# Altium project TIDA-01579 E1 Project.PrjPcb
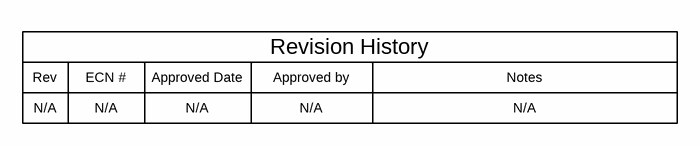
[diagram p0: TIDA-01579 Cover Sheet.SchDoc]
CopyrightYear: 2018; PCB_Layout: Barrett Bryan; PCB_Rev: E1; PRJ_Customer: Public Release; PRJ_Engineer: Srinivasan Iyer; PRJ_Number: TIDA-01579; PRJ_Title: TIDA-01579 Video Doorbell Power; SCH_Rev: E1; TechSupport: http://www.ti.com/support; TID: TIDA-01579
4 sheets, 208 parts. Net scope: global (net labels, ports and power ports of the same name join across sheets).
Board file: PCB-08.PcbDoc
Sheets:
  TIDA-01579 Cover Sheet.SchDoc
  TIDA-01579 Point of Load.SchDoc
  TIDA-01579 Other.SchDoc
  EVM_Hardware.SchDoc

## Sheet TIDA-01579 Cover Sheet.SchDoc
size 431 x 279 mm; Date: Not shown in title block; ApprovedBy: Not shown in title block; CheckedBy: Not shown in title block; Author: Not shown in title block; CompanyName: Not shown in title block; Engineer: Not shown in title block; Organization: Not shown in title block; Address1: Not shown in title block; Address2: Not shown in title block; Address3: Not shown in title block; Address4: Not shown in title block; DocumentNumber: 1; Revision: Use project parameter SCH_Rev; SheetNumber: 1; SheetTotal: 3; PageSetup: Record=PageOptions¦CenterHorizontal=True¦CenterVertical=True¦PrintScale=1.00¦XCorrection=1.00¦YCorrection=1.00¦PrintKind=0¦BorderSize=5000000¦LeftOffset=0¦BottomOffset=0¦Orientation=2¦PaperLength=1000¦PaperWidth=1000¦Scale=100¦PaperSource=15¦PrintQuality=600¦MediaType=1¦DitherType=10¦PaperKind=Letter¦PrintScaleMode=1

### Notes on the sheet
- Rev
- N/A
- ECN #
- Approved Date
- Approved by
- Revision History
- Notes

## Sheet TIDA-01579 Point of Load.SchDoc: Point of load converters
size 431 x 279 mm; Date: Not shown in title block; ApprovedBy: Not shown in title block; CheckedBy: Not shown in title block; Author: Not shown in title block; CompanyName: Not shown in title block; DrawnBy: Barrett Bryan; Engineer: Not shown in title block; Organization: Not shown in title block; Address1: Not shown in title block; Address2: Not shown in title block; Address3: Not shown in title block; Address4: Not shown in title block; DocumentNumber: 1; Revision: Use project parameter SCH_Rev; SheetNumber: 2; SheetTotal: 3; PageSetup: Record=PageOptions¦CenterHorizontal=True¦CenterVertical=True¦PrintScale=1.00¦XCorrection=1.00¦YCorrection=1.00¦PrintKind=0¦BorderSize=5000000¦LeftOffset=0¦BottomOffset=0¦Orientation=2¦PaperLength=1000¦PaperWidth=1000¦Scale=100¦PaperSource=15¦PrintQuality=600¦MediaType=1¦DitherType=10¦PaperKind=Letter¦PrintScaleMode=1
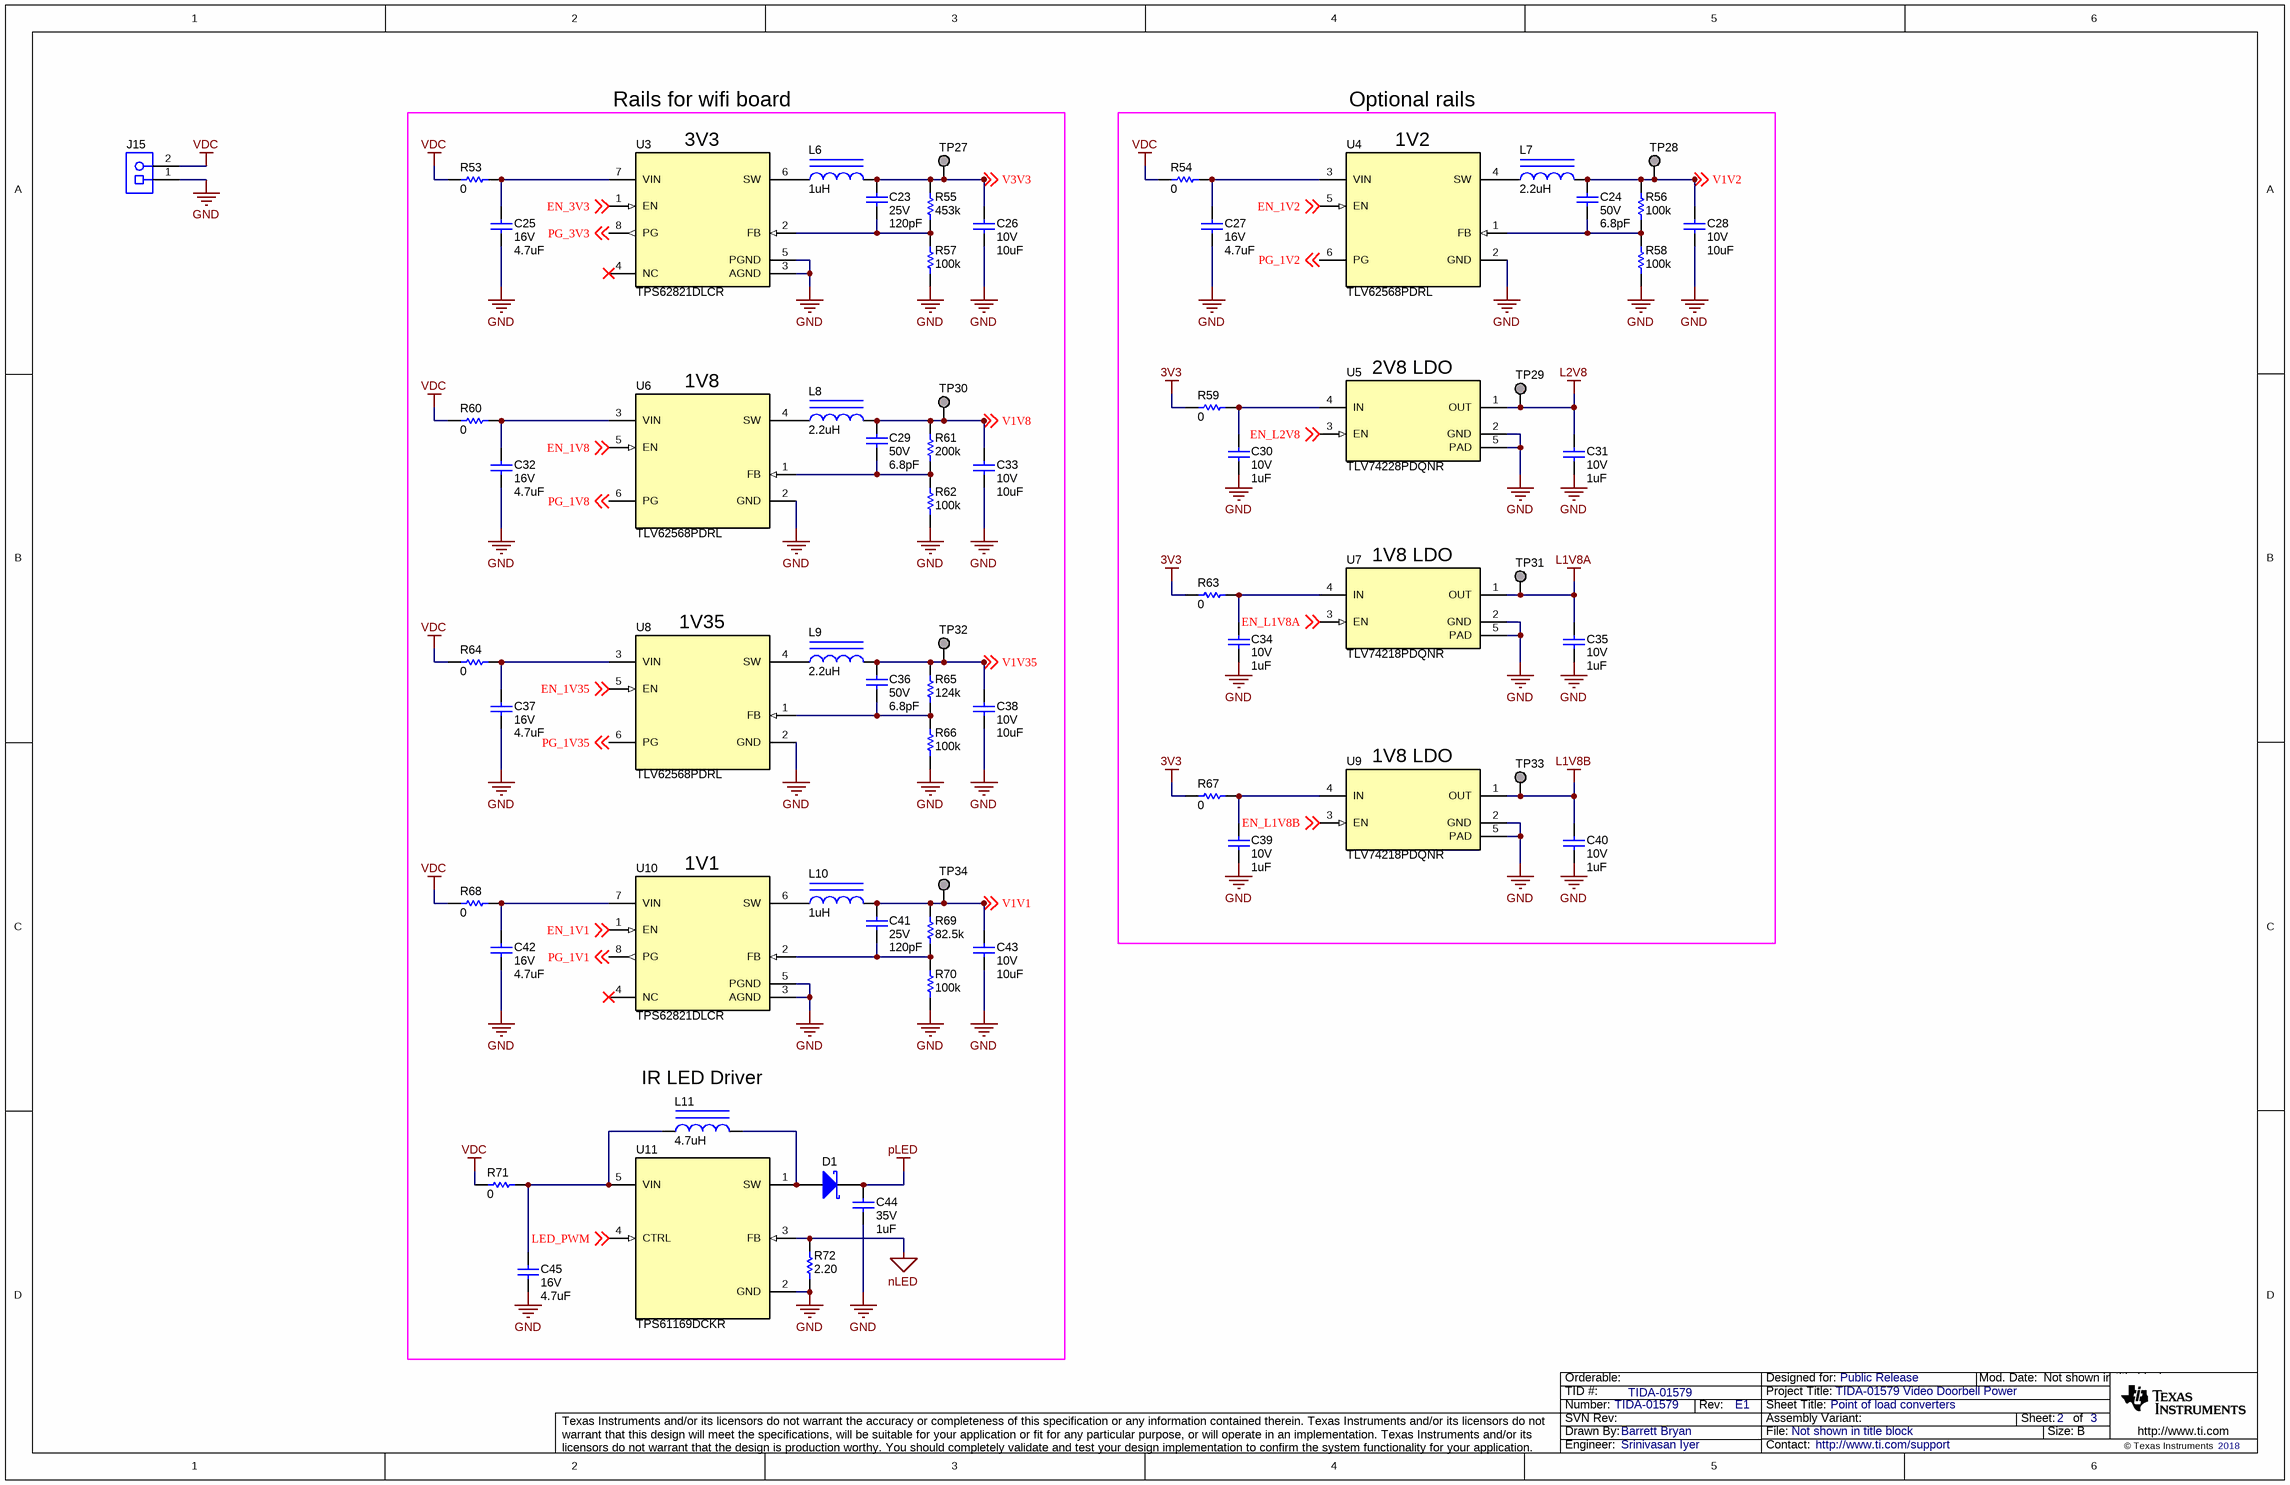
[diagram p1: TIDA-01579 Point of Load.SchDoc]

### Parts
C23  VDC_V: 25V  ValueDisplayed: 120pF  [0201]  (hidden comment: GRM033R71E121KA01D)
C24  VDC_V: 50V  ValueDisplayed: 6.8pF  [0201]  (hidden comment: GRM0335C1H6R8BA01D)
C25  VDC_V: 16V  ValueDisplayed: 4.7uF  [0603S]  (hidden comment: GRM188Z71C475KE21D)
C26  VDC_V: 10V  ValueDisplayed: 10uF  [0603]  (hidden comment: GRM188Z71A106MA73D)
C27  VDC_V: 16V  ValueDisplayed: 4.7uF  [0603]  (hidden comment: GRM188Z71C475KE21D)
C28  VDC_V: 10V  ValueDisplayed: 10uF  [0603]  (hidden comment: GRM188Z71A106MA73D)
C29  VDC_V: 50V  ValueDisplayed: 6.8pF  [0201]  (hidden comment: GRM0335C1H6R8BA01D)
C30  VDC_V: 10V  ValueDisplayed: 1uF  [0402]  (hidden comment: GRM155R61A105KE15D)
C31  VDC_V: 10V  ValueDisplayed: 1uF  [0402]  (hidden comment: GRM155R61A105KE15D)
C32  VDC_V: 16V  ValueDisplayed: 4.7uF  [0603]  (hidden comment: GRM188Z71C475KE21D)
C33  VDC_V: 10V  ValueDisplayed: 10uF  [0603]  (hidden comment: GRM188Z71A106MA73D)
C34  VDC_V: 10V  ValueDisplayed: 1uF  [0402]  (hidden comment: GRM155R61A105KE15D)
C35  VDC_V: 10V  ValueDisplayed: 1uF  [0402]  (hidden comment: GRM155R61A105KE15D)
C36  VDC_V: 50V  ValueDisplayed: 6.8pF  [0201]  (hidden comment: GRM0335C1H6R8BA01D)
C37  VDC_V: 16V  ValueDisplayed: 4.7uF  [0603]  (hidden comment: GRM188Z71C475KE21D)
C38  VDC_V: 10V  ValueDisplayed: 10uF  [0603]  (hidden comment: GRM188Z71A106MA73D)
C39  VDC_V: 10V  ValueDisplayed: 1uF  [0402]  (hidden comment: GRM155R61A105KE15D)
C40  VDC_V: 10V  ValueDisplayed: 1uF  [0402]  (hidden comment: GRM155R61A105KE15D)
C41  VDC_V: 25V  ValueDisplayed: 120pF  [0201]  (hidden comment: GRM033R71E121KA01D)
C42  VDC_V: 16V  ValueDisplayed: 4.7uF  [0603S]  (hidden comment: GRM188Z71C475KE21D)
C43  VDC_V: 10V  ValueDisplayed: 10uF  [0603]  (hidden comment: GRM188Z71A106MA73D)
C44  VDC_V: 35V  ValueDisplayed: 1uF  [0603]  (hidden comment: C1608X7R1V105K080AC)
C45  VDC_V: 16V  ValueDisplayed: 4.7uF  [0603]  (hidden comment: GRM188Z71C475KE21D)
D1  NSR0240V2T1G  [SOD-523]  (value not drawn)
J15  2059-302/998-403  [WAGO_2059-302]  (value not drawn)
L6  ValueDisplayed: 1uH  [WE-PMCI_0805]  (hidden comment: 74479275210)
L7  ValueDisplayed: 2.2uH  [DFE252012P]  (hidden comment: DFE252012P-2R2M=P2)
L8  ValueDisplayed: 2.2uH  [DFE252012P]  (hidden comment: DFE252012P-2R2M=P2)
L9  ValueDisplayed: 2.2uH  [DFE252012P]  (hidden comment: DFE252012P-2R2M=P2)
L10  ValueDisplayed: 1uH  [WE-PMCI_0805]  (hidden comment: 74479275210)
L11  ValueDisplayed: 4.7uH  [DFE252012P]  (hidden comment: DFE252012PD-4R7M)
R53  ValueDisplayed: 0  [0402S]  (hidden comment: RC0402JR-070RL)
R54  ValueDisplayed: 0  [0402S]  (hidden comment: RC0402JR-070RL)
R55  ValueDisplayed: 453k  [0201]  (hidden comment: RC0201FR-07453KL)
R56  ValueDisplayed: 100k  [0201]  (hidden comment: RC0201FR-07100KL)
R57  ValueDisplayed: 100k  [0201]  (hidden comment: RC0201FR-07100KL)
R58  ValueDisplayed: 100k  [0201]  (hidden comment: RC0201FR-07100KL)
R59  ValueDisplayed: 0  [0402S]  (hidden comment: RC0402JR-070RL)
R60  ValueDisplayed: 0  [0402S]  (hidden comment: RC0402JR-070RL)
R61  ValueDisplayed: 200k  [0201]  (hidden comment: RC0201FR-7D200KL)
R62  ValueDisplayed: 100k  [0201]  (hidden comment: RC0201FR-07100KL)
R63  ValueDisplayed: 0  [0402S]  (hidden comment: RC0402JR-070RL)
R64  ValueDisplayed: 0  [0402S]  (hidden comment: RC0402JR-070RL)
R65  ValueDisplayed: 124k  [0201]  (hidden comment: RC0201FR-07124KL)
R66  ValueDisplayed: 100k  [0201]  (hidden comment: RC0201FR-07100KL)
R67  ValueDisplayed: 0  [0402S]  (hidden comment: RC0402JR-070RL)
R68  ValueDisplayed: 0  [0402S]  (hidden comment: RC0402JR-070RL)
R69  ValueDisplayed: 82.5k  [0201]  (hidden comment: RC0201FR-0782K5L)
R70  ValueDisplayed: 100k  [0201]  (hidden comment: RC0201FR-07100KL)
R71  ValueDisplayed: 0  [0402S]  (hidden comment: RC0402JR-070RL)
R72  ValueDisplayed: 2.20  [0402]  (hidden comment: RCS04022R20FKED)
TP27  RCU-0C  [TE_RCU]  (value not drawn)
TP28  RCU-0C  [TE_RCU]  (value not drawn)
TP29  RCU-0C  [TE_RCU]  (value not drawn)
TP30  RCU-0C  [TE_RCU]  (value not drawn)
TP31  RCU-0C  [TE_RCU]  (value not drawn)
TP32  RCU-0C  [TE_RCU]  (value not drawn)
TP33  RCU-0C  [TE_RCU]  (value not drawn)
TP34  RCU-0C  [TE_RCU]  (value not drawn)
U3  TPS62821DLCR  [DLC0008A]
U4  TLV62568PDRL  [DRL0006A]
U5  TLV74228PDQNR  [DQN0004A]
U6  TLV62568PDRL  [DRL0006A]
U7  TLV74218PDQNR  [DQN0004A]
U8  TLV62568PDRL  [DRL0006A]
U9  TLV74218PDQNR  [DQN0004A]
U10  TPS62821DLCR  [DLC0008A]
U11  TPS61169DCKR  [DCK0005A_N]

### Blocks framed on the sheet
Rails for wifi board: C23 C25 C26 C29 C32 C33 C36-C38 C41-C45 D1 L6 L8-L11 R53 R55 R57 R60-R62 R64-R66 R68-R72 TP27 TP30 TP32 TP34 U3 U6 U8 U10 U11
Optional rails: C24 C27 C28 C30 C31 C34 C35 C39 C40 L7 R54 R56 R58 R59 R63 R67 TP28 TP29 TP31 TP33 U4 U5 U7 U9

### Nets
3V3: R59.1 R63.1 R67.1
GND: C25.2 C26.2 C27.2 C28.2 C30.2 C31.2 C32.2 C33.2 C34.2 C35.2 C37.2 C38.2 C39.2 C40.2 C42.2 C43.2 C44.2 C45.2 J15.1 R57.2 R58.2 R62.2 R66.2 R70.2 R72.2 U3.3(AGND) U3.5(PGND) U4.2(GND) U5.2(GND) U5.5(PAD) U6.2(GND) U7.2(GND) U7.5(PAD) U8.2(GND) U9.2(GND) U9.5(PAD) U10.3(AGND) U10.5(PGND) U11.2(GND)
L1V8A: C35.1 TP31.1 U7.1(OUT)
L1V8B: C40.1 TP33.1 U9.1(OUT)
L2V8: C31.1 TP29.1 U5.1(OUT)
nLED: R72.1 U11.3(FB)
pLED: C44.1 D1.1(K)
VDC: J15.2 R53.1 R54.1 R60.1 R64.1 R68.1 R71.1  [project net PLLUP]
EN_1V1: U10.1(EN) ; off-sheet EN_1V1
EN_1V2: U4.5(EN) ; off-sheet EN_1V2
EN_1V8: U6.5(EN) ; off-sheet EN_1V8
EN_1V35: U8.5(EN) ; off-sheet EN_1V35
EN_3V3: U3.1(EN) ; off-sheet EN_3V3
EN_L1V8A: U7.3(EN) ; off-sheet EN_L1V8A
EN_L1V8B: U9.3(EN) ; off-sheet EN_L1V8B
EN_L2V8: U5.3(EN) ; off-sheet EN_L2V8
LED_PWM: U11.4(CTRL) ; off-sheet LED_PWM
PG_1V1: U10.8(PG) ; off-sheet PG_1V1
PG_1V2: U4.6(PG) ; off-sheet PG_1V2
PG_1V8: U6.6(PG) ; off-sheet PG_1V8
PG_1V35: U8.6(PG) ; off-sheet PG_1V35
PG_3V3: U3.8(PG) ; off-sheet PG_3V3
V1V1: C41.1 C43.1 L10.2 R69.1 TP34.1 ; off-sheet V1V1
V1V2: C24.1 C28.1 L7.2 R56.1 TP28.1 ; off-sheet V1V2
V1V8: C29.1 C33.1 L8.2 R61.1 TP30.1 ; off-sheet V1V8
V1V35: C36.1 C38.1 L9.2 R65.1 TP32.1 ; off-sheet V1V35
V3V3: C23.1 C26.1 L6.2 R55.1 TP27.1 ; off-sheet V3V3
NetC23_2: C23.2 R55.2 R57.1 U3.2(FB)
NetC24_2: C24.2 R56.2 R58.1 U4.1(FB)
NetC25_1: C25.1 R53.2 U3.7(VIN)
NetC27_1: C27.1 R54.2 U4.3(VIN)
NetC29_2: C29.2 R61.2 R62.1 U6.1(FB)
NetC30_1: C30.1 R59.2 U5.4(IN)
NetC32_1: C32.1 R60.2 U6.3(VIN)
NetC34_1: C34.1 R63.2 U7.4(IN)
NetC36_2: C36.2 R65.2 R66.1 U8.1(FB)
NetC37_1: C37.1 R64.2 U8.3(VIN)
NetC39_1: C39.1 R67.2 U9.4(IN)
NetC41_2: C41.2 R69.2 R70.1 U10.2(FB)
NetC42_1: C42.1 R68.2 U10.7(VIN)
NetC45_1: C45.1 L11.1 R71.2 U11.5(VIN)
NetD1_2: D1.2(A) L11.2 U11.1(SW)
NetL6_1: L6.1 U3.6(SW)
NetL7_1: L7.1 U4.4(SW)
NetL8_1: L8.1 U6.4(SW)
NetL9_1: L9.1 U8.4(SW)
NetL10_1: L10.1 U10.6(SW)

Not connected (* = marked no-connect by the designer): U3 4(NC)*; U10 4(NC)*

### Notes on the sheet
- (near U3) 3V3
- (near U4) 1V2
- (near U5) 2V8 LDO
- (near U6) 1V8
- (near U7) 1V8 LDO
- (near U8) 1V35
- (near U9) 1V8 LDO
- (near U10) 1V1
- (near L11) IR LED Driver

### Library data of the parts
C23 C41 = CMP-0009765-1: CAP, CERM, 120 pF, 25 V, +/- 10%, X7R, 0201; Manufacturer: MuRata; TaMin_C: -55°C; Polarized: N; SizeAreaWB_mm2: 2.08; Value1: Unknown; U/M: EA; Value: 120pF; TaMax_C: 125°C; SizeZ_mm: 0.26; SizeX_mm: 0.6; SizeY_mm: 0.3; SizeArea_mm2: 0.18; AEC Category: Q200
C24 C29 C36 = CMP-0009669-4: CAP, CERM, 6.8 pF, 50 V, +/- 2%, C0G/NP0, 0201; Manufacturer: MuRata; TaMin_C: -55°C; Polarized: N; SizeAreaWB_mm2: 2.08; Value1: Unknown; U/M: EA; Value: 6.8pF; TaMax_C: 125°C; SizeZ_mm: 0.26; SizeX_mm: 0.6; SizeY_mm: 0.3; SizeArea_mm2: 0.18; AEC Category: Q200
C25 C42 = CMP-0064936-4: CAP, CERM, 4.7 uF, 16 V,+/- 10%, X7R, 0603; Manufacturer: MuRata; TaMin_C: -55°C; Polarized: N; SizeAreaWB_mm2: 4.68; Value1: Unknown; U/M: EA; Value: 4.7uF; TaMax_C: 125°C; SizeZ_mm: 1; SizeX_mm: 1.6; SizeY_mm: 0.8; Cap_Case: 0603; SizeArea_mm2: 1.28; Cap_F: 4.7µF; AEC Category: Q200
C26 = CMP-0007497-5: CAP, CERM, 10 uF, 10 V, +/- 20%, X7R, 0603; Manufacturer: MuRata; SizeY_mm: 0.8; SizeArea_mm2: 1.28; CompType: Capacitor; AEC Qualified: N; Cap_F: 10µF; AEC Category: Q200; TaMin_C: -55°C; SizeAreaWB_mm2: 4.68; Value1: Unknown; U/M: EA; Value: 10uF; TaMax_C: 125°C; SizeZ_mm: 1; SizeX_mm: 1.6
C27 C32 C37 C45 = CMP-0064936-4: CAP, CERM, 4.7 uF, 16 V,+/- 10%, X7R, 0603; Manufacturer: MuRata; TaMin_C: -55°C; Polarized: N; SizeAreaWB_mm2: 4.68; Value1: Unknown; U/M: EA; Value: 4.7uF; TaMax_C: 125°C; SizeZ_mm: 1; SizeX_mm: 1.6; SizeY_mm: 0.8; SizeArea_mm2: 1.28; Cap_F: 4.7µF; AEC Category: Q200
C28 C33 C38 C43 = CMP-0007497-5: CAP, CERM, 10 uF, 10 V, +/- 20%, X7R, 0603; Manufacturer: MuRata; SizeY_mm: 0.8; SizeArea_mm2: 1.28; AEC Qualified: N; Cap_F: 10µF; AEC Category: Q200; TaMin_C: -55°C; SizeAreaWB_mm2: 4.68; Value1: Unknown; U/M: EA; Value: 10uF; TaMax_C: 125°C; SizeZ_mm: 1; SizeX_mm: 1.6
C30 C31 C34 C35 C39 C40 = CMP-0006563-2: CAP, CERM, 1 uF, 10 V, +/- 10%, X5R, 0402; Manufacturer: MuRata; TaMin_C: -55°C; Polarized: N; SizeAreaWB_mm2: 3; Value1: Unknown; U/M: EA; Value: 1uF; TaMax_C: 85°C; SizeZ_mm: 0.6; SizeX_mm: 1; SizeY_mm: 0.5; Cap_F: 1µF; AEC Category: Q200
C44 = CMP-0007052-4: CAP, CERM, 1 uF, 35 V, +/- 10%, X7R, 0603; Manufacturer: TDK; TaMin_C: -55°C; Polarized: N; SizeAreaWB_mm2: 4.68; Value1: Unknown; U/M: EA; Value: 1uF; TaMax_C: 125°C; SizeZ_mm: 1; SizeX_mm: 1.6; SizeY_mm: 0.8; SizeArea_mm2: 1.28; Cap_F: 1µF; AEC Category: Q200
D1 = CMP-0028616-2: Diode, Schottky, 40 V, 0.25 A, SOD-523; Manufacturer: ON Semiconductor; Io_A: 2.5dA; Green_Lifecycle: Active; SizeAreaWB_mm2: 5.13; Vr_V: 40V; Green_REACh: Passed; Value1: 0.25A; TJmax_C: 150°C; U/M: EA; Value: 40V; SizeZ_mm: 0.65; SizeX_mm: 1.7; SizeY_mm: 0.9; Vf_V: 7dV; Value2: 0.7V; SizeArea_mm2: 1.53; AEC Category: Q101
J15 = CMP-0075342-1: Terminal Block, 3mm, 2-pole, Tin, SMD; Manufacturer: WAGO; CNHeader: False; Current_A: 3A; Gender: Female; Pitch_mm: 3; CT: True
L6 L10 = CMP-0064308-1: Inductor, Shielded, 1 uH, 1.8 A, 0.078 ohm, SMD; Manufacturer: Wurth Elektronik; Isat: 2.1A @ 30% inductance drop; Irms: 1.8A @ 40C rise; Green_Lifecycle: Active; SizeAreaWB_mm2: 6.75; DCR_ohm: 0.078; Green_REACh: Passed; Value: 1uH; Imax_A: 1.8A; SizeZ_mm: 1; SizeX_mm: 2; SizeY_mm: 1.25; SizeArea_mm2: 2.5; Ind_H: 1µH; AEC Qualified: N; AEC Category: Q200
L7-L9 = CMP-0058936-1: Inductor, Shielded, 2.2 uH, 2.6 A, 0.07 ohm, SMD; Manufacturer: MuRata Toko; Isat: 3.3A @ 30% inductance drop; Irms: 2.6A @ 40C rise; SizeAreaWB_mm2: 10.5; DCR_ohm: 0.07; Value: 2.2uH; Imax_A: 2.6A; SizeZ_mm: 1.2; SizeX_mm: 2.5; SizeY_mm: 2; SizeArea_mm2: 5; Ind_H: 2.2µH; AEC Category: Q200
L11 = CMP-0058942-1: Inductor, Shielded, Metal Composite, 4.7 uH, 1.4 A, 0.165 ohm, AEC-Q200 Grade 1, SMD; Manufacturer: MuRata Toko; Isat: 1.9A @ 30% inductance drop; Irms: 1.4A @ 40C rise; SizeAreaWB_mm2: 10.5; DCR_ohm: 1.65d; Value: 4.7uH; Imax_A: 1.4A; SizeZ_mm: 1.2; SizeX_mm: 2.5; SizeY_mm: 2; SizeArea_mm2: 5; Ind_H: 4.7µH; AEC Qualified: Y; AEC Grade: 1; AEC Category: Q200
R53 R54 R59 R60 R63 R64 R67 R68 R71 = CMP-0027004-2: RES, 0, 5%, 0.063 W, 0402; Manufacturer: Yageo America; Power_W: 63mW; TempCo: 200 ppm/C; Value_Code: 0000; U/M: EA; Value: 0; EIA_Code: E24; SizeX_mm: 1; SizeY_mm: 0.5; SizeZ_mm: 0.6; Value2: 0.063W; VDC_V: 50V; AEC Category: Q200
R55 = CMP-0027710-1: RES, 453 k, 1%, 0.05 W, 0201; Manufacturer: Yageo America; Power_W: 50mW; TempCo: 200 ppm/C; U/M: EA; Value: 453k; EIA_Code: E96; SizeX_mm: 0.6; SizeY_mm: 0.3; SizeZ_mm: 0.26; Value2: 0.05W; SizeArea_mm2: 0.18; AEC Qualified: N; VDC_V: 25V; AEC Category: Q200
R56-R58 R62 R66 R70 = CMP-0027293-2: RES, 100 k, 1%, 0.05 W, 0201; Manufacturer: Yageo America; Power_W: 50mW; TempCo: 200 ppm/C; U/M: EA; Value: 100k; EIA_Code: E96; SizeX_mm: 0.6; SizeY_mm: 0.3; SizeZ_mm: 0.26; Value2: 0.05W; SizeArea_mm2: 0.18; AEC Qualified: N; VDC_V: 25V; AEC Category: Q200
R61 = CMP-0027976-1: RES, 200 k, 1%, 0.05 W, 0201; Manufacturer: Yageo America; Power_W: 50mW; TempCo: 200 ppm/C; U/M: EA; Value: 200k; EIA_Code: E96; SizeX_mm: 0.6; SizeY_mm: 0.3; SizeZ_mm: 0.26; Value2: 0.05W; SizeArea_mm2: 0.18; AEC Qualified: N; VDC_V: 25V; AEC Category: Q200
R65 = CMP-0027330-2: RES, 124 k, 1%, 0.05 W, 0201; Manufacturer: Yageo America; Power_W: 50mW; TempCo: 200 ppm/C; U/M: EA; Value: 124k; EIA_Code: E96; SizeX_mm: 0.6; SizeY_mm: 0.3; SizeZ_mm: 0.26; Value2: 0.05W; SizeArea_mm2: 0.18; AEC Qualified: N; VDC_V: 25V; AEC Category: Q200
R69 = CMP-0027891-1: RES, 82.5 k, 1%, 0.05 W, 0201; Manufacturer: Yageo America; Power_W: 50mW; TempCo: 200 ppm/C; Value_Code: 82k5; U/M: EA; Value: 82.5k; EIA_Code: E96; SizeX_mm: 0.6; SizeY_mm: 0.3; SizeZ_mm: 0.26; Value2: 0.05W; SizeArea_mm2: 0.18; AEC Qualified: N; VDC_V: 25V; AEC Category: Q200
R72 = CMP-0026747-1: RES, 2.20, 1%, 0.2 W, 0402; Manufacturer: Vishay-Dale; Power_W: 200mW; TempCo: 100 ppm/C; Value_Code: 2R20; U/M: EA; Value: 2.20; Res_ohm: 2.2; SizeX_mm: 1; SizeY_mm: 0.5; SizeZ_mm: 0.6; Value2: 0.2W; AEC Qualified: N; AEC Category: Q200
TP27-TP34 = CMP-0067620-1: PC Test Point, SMT; Manufacturer: TE Connectivity
U3 U10 = CMP-0065148-3: 1A Step-Down Converter With 1% Accuracy, DLC0008A (VSON-HR-8); Manufacturer: Texas Instruments; SizeX_mm: 1.5; SizeY_mm: 2.0; CompType: IC; SizeZ_mm: 1.0; SizeArea_mm2: 3.0; SizeAreaWB_mm2: 7.5; AEC Category: Q200; AEC Qualified: N
U4 U6 U8 = CMP-0013406-3: 1-A High Efficiency Step-Down Converter in SOT Package, DRL0006A (SOT-6); Manufacturer: Texas Instruments; SizeZ_mm: 0.6; SizeX_mm: 1.6; SizeArea_mm2: 2.56; CompType: IC; U/M: EA; SizeAreaWB_mm2: 6.76
U5 = CMP-0079104-2: 200-mA, Small Size, Low-Dropout Linear Voltage Regulator, DQN0004A (X2SON-4); Alternate Manufacturer: Texas Instruments; SizeAreaWB_mm2: 4; SizeZ_mm: 0.4; SizeX_mm: 1; CompType: IC; AEC Qualified: N; AEC Category: Q200
U7 U9 = CMP-0079107-2: 200-mA, Small Size, Low-Dropout Linear Voltage Regulator, DQN0004A (X2SON-4); Alternate Manufacturer: Texas Instruments; SizeAreaWB_mm2: 4; SizeZ_mm: 0.4; SizeX_mm: 1; CompType: IC; AEC Qualified: N; AEC Category: Q200
U11 = CMP-0073719-2: TPS61169 38-V High-Current Boost WLED Driver, DCK0005A (SOT-SC70-5); Alternate Manufacturer: Texas Instruments; Green_Lifecycle: Active; SizeAreaWB_mm2: 9.3; Green_REACh: Passed; SizeZ_mm: 1.1; SizeX_mm: 2.1; SizeY_mm: 2.0; SizeArea_mm2: 4.2; CompType: IC; AEC Category: Q200; AEC Qualified: N

## Sheet TIDA-01579 Other.SchDoc
size 431 x 279 mm; Date: Not shown in title block; ApprovedBy: Not shown in title block; CheckedBy: Not shown in title block; Author: Not shown in title block; CompanyName: Not shown in title block; Engineer: Not shown in title block; Organization: Not shown in title block; Address1: Not shown in title block; Address2: Not shown in title block; Address3: Not shown in title block; Address4: Not shown in title block; DocumentNumber: 1; Revision: Use project parameter SCH_Rev; SheetNumber: 2; SheetTotal: 3; PageSetup: Record=PageOptions¦CenterHorizontal=True¦CenterVertical=True¦PrintScale=1.00¦XCorrection=1.00¦YCorrection=1.00¦PrintKind=0¦BorderSize=5000000¦LeftOffset=0¦BottomOffset=0¦Orientation=2¦PaperLength=1000¦PaperWidth=1000¦Scale=100¦PaperSource=15¦PrintQuality=600¦MediaType=1¦DitherType=10¦PaperKind=Letter¦PrintScaleMode=1
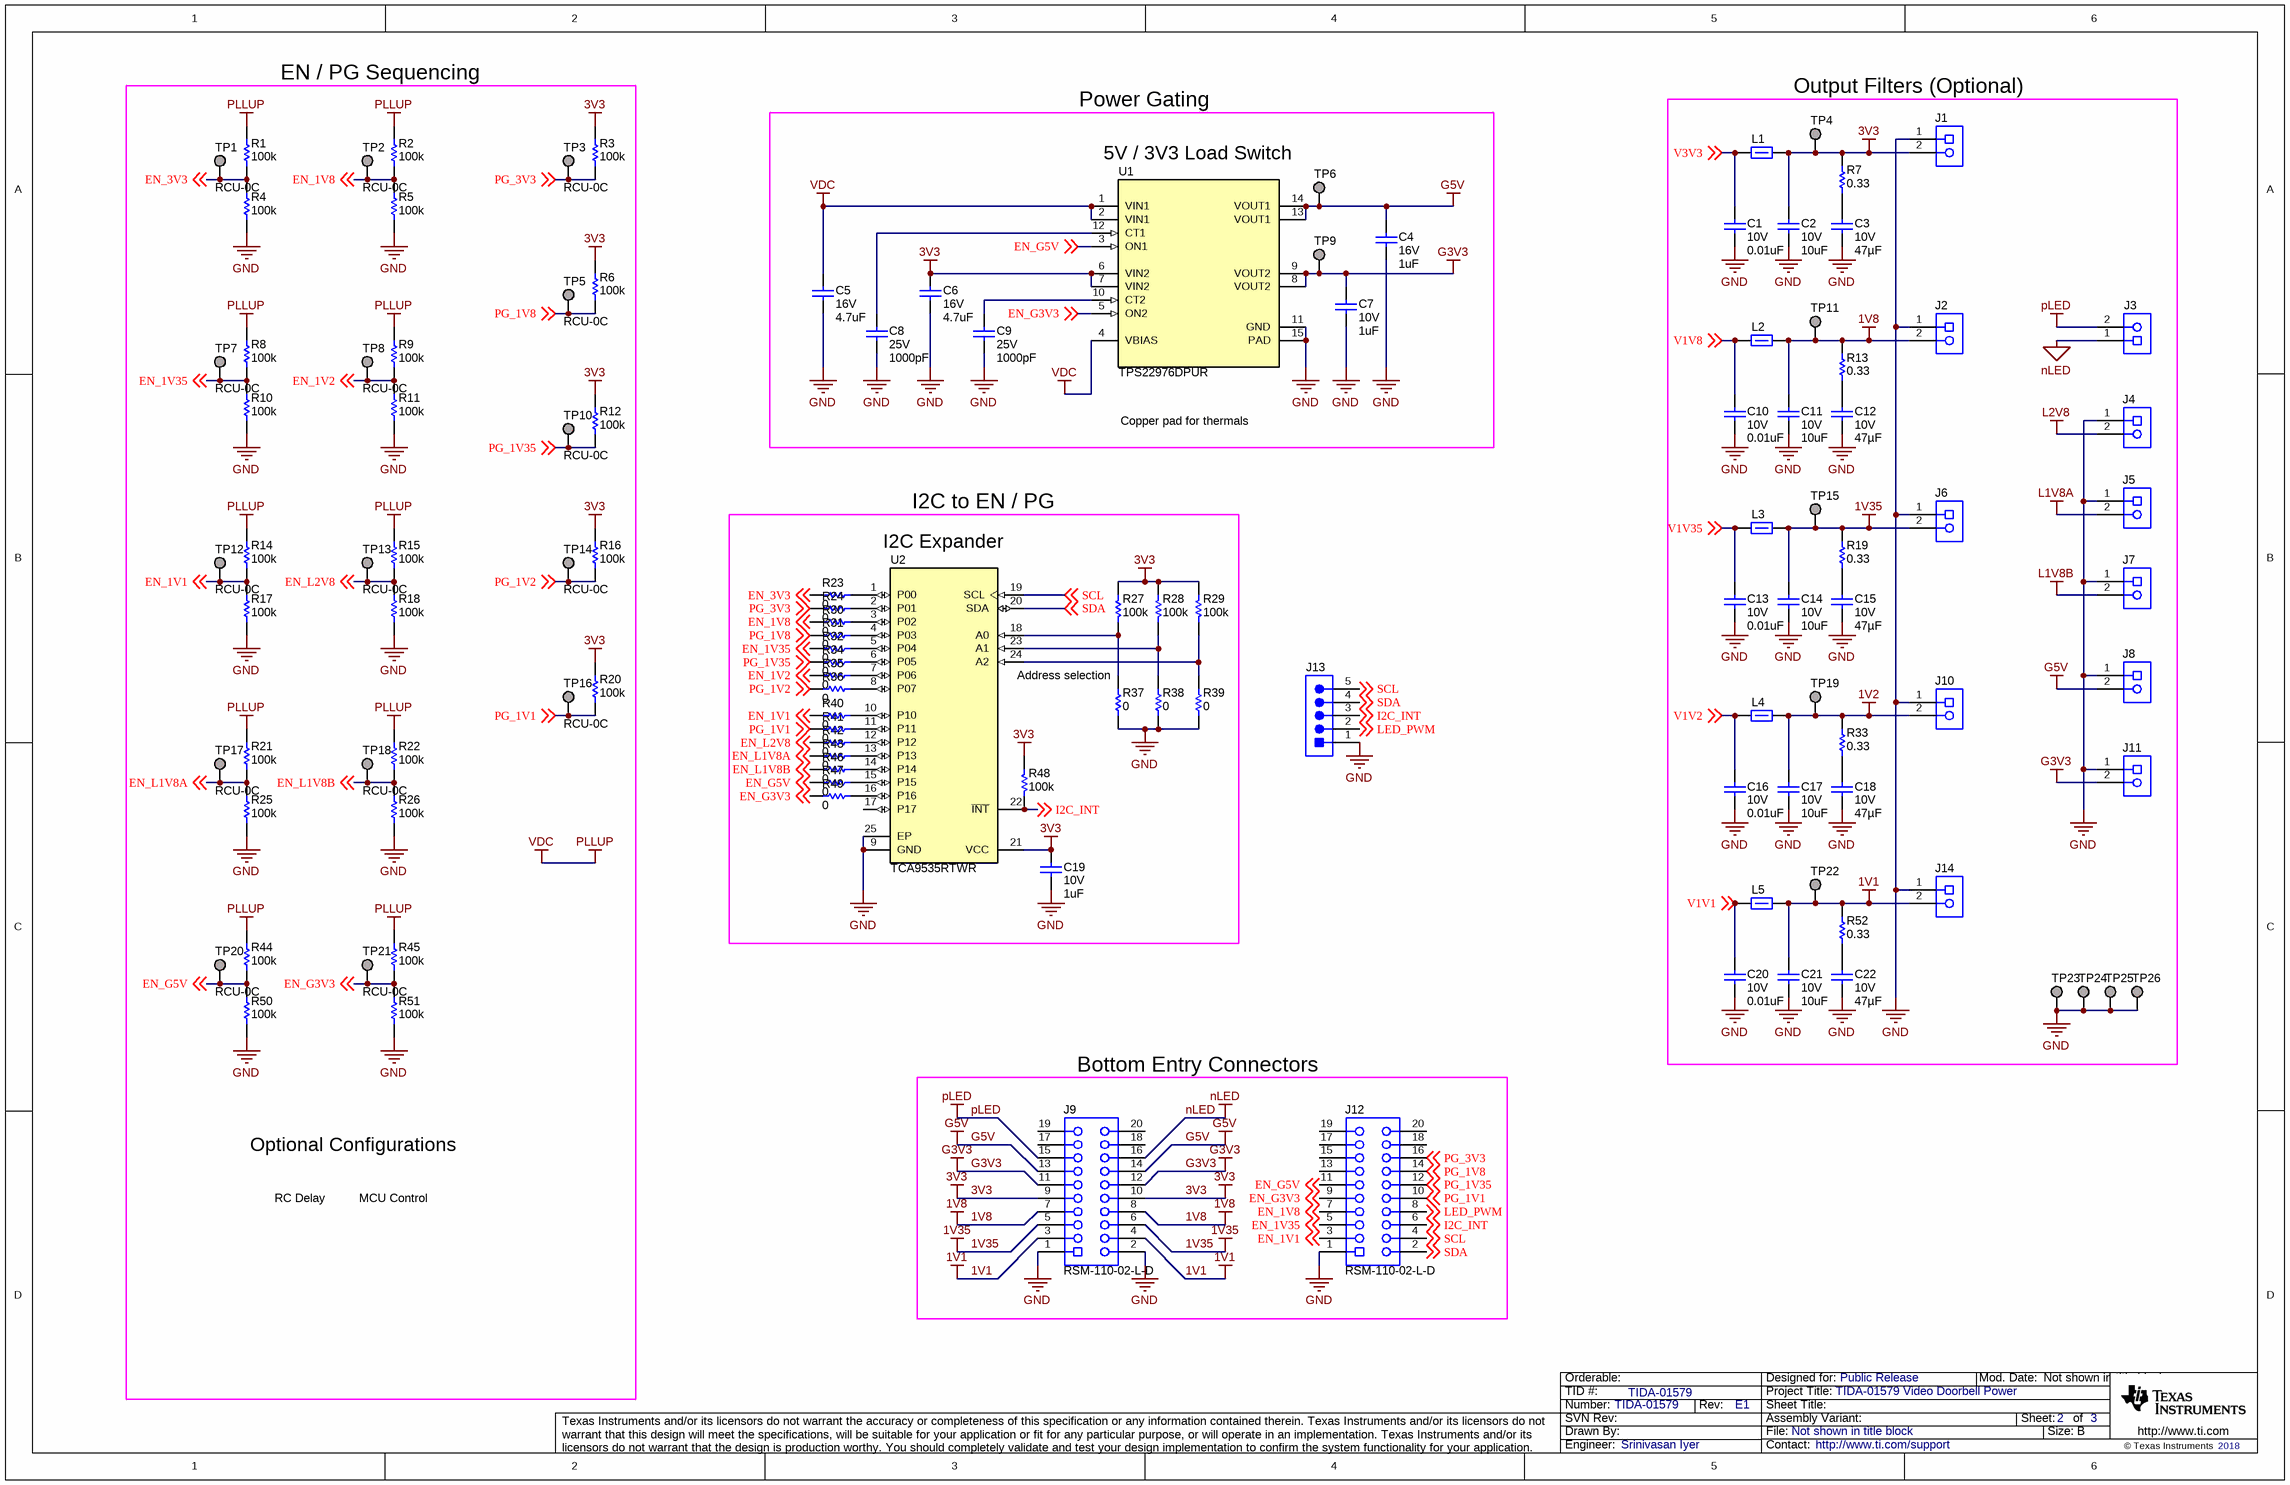
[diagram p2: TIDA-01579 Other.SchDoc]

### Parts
C1  VDC_V: 10V  ValueDisplayed: 0.01uF  [0402]  (hidden comment: 0402ZC103KAT2A)
C2  VDC_V: 10V  ValueDisplayed: 10uF  [0603]  (hidden comment: GRM188R61A106ME69D)
C3  VDC_V: 10V  ValueDisplayed: 47µF  [0805_HV]  (hidden comment: GRM21BR61A476ME15L)
C4  VDC_V: 16V  ValueDisplayed: 1uF  [0603]  (hidden comment: GRM188R71C105KA12D)
C5  VDC_V: 16V  ValueDisplayed: 4.7uF  [0603]  (hidden comment: GRM188Z71C475KE21D)
C6  VDC_V: 16V  ValueDisplayed: 4.7uF  [0603]  (hidden comment: GRM188Z71C475KE21D)
C7  VDC_V: 10V  ValueDisplayed: 1uF  [0603]  (hidden comment: GRM188R71A105KA61D)
C8  VDC_V: 25V  ValueDisplayed: 1000pF  [0201_033]  (hidden comment: C0603X5R1E102K030BA)
C9  VDC_V: 25V  ValueDisplayed: 1000pF  [0201_033]  (hidden comment: C0603X5R1E102K030BA)
C10  VDC_V: 10V  ValueDisplayed: 0.01uF  [0402]  (hidden comment: 0402ZC103KAT2A)
C11  VDC_V: 10V  ValueDisplayed: 10uF  [0603]  (hidden comment: GRM188R61A106ME69D)
C12  VDC_V: 10V  ValueDisplayed: 47µF  [0805_HV]  (hidden comment: GRM21BR61A476ME15L)
C13  VDC_V: 10V  ValueDisplayed: 0.01uF  [0402]  (hidden comment: 0402ZC103KAT2A)
C14  VDC_V: 10V  ValueDisplayed: 10uF  [0603]  (hidden comment: GRM188R61A106ME69D)
C15  VDC_V: 10V  ValueDisplayed: 47µF  [0805_HV]  (hidden comment: GRM21BR61A476ME15L)
C16  VDC_V: 10V  ValueDisplayed: 0.01uF  [0402]  (hidden comment: 0402ZC103KAT2A)
C17  VDC_V: 10V  ValueDisplayed: 10uF  [0603]  (hidden comment: GRM188R61A106ME69D)
C18  VDC_V: 10V  ValueDisplayed: 47µF  [0805_HV]  (hidden comment: GRM21BR61A476ME15L)
C19  VDC_V: 10V  ValueDisplayed: 1uF  [0402]  (hidden comment: GRM155R61A105ME15D)
C20  VDC_V: 10V  ValueDisplayed: 0.01uF  [0402]  (hidden comment: 0402ZC103KAT2A)
C21  VDC_V: 10V  ValueDisplayed: 10uF  [0603]  (hidden comment: GRM188R61A106ME69D)
C22  VDC_V: 10V  ValueDisplayed: 47µF  [0805_HV]  (hidden comment: GRM21BR61A476ME15L)
J1  2059-302/998-403  [WAGO_2059-302]  (value not drawn)
J2  2059-302/998-403  [WAGO_2059-302]  (value not drawn)
J3  2059-302/998-403  [WAGO_2059-302]  (value not drawn)
J4  2059-302/998-403  [WAGO_2059-302]  (value not drawn)
J5  2059-302/998-403  [WAGO_2059-302]  (value not drawn)
J6  2059-302/998-403  [WAGO_2059-302]  (value not drawn)
J7  2059-302/998-403  [WAGO_2059-302]  (value not drawn)
J8  2059-302/998-403  [WAGO_2059-302]  (value not drawn)
J9  RSM-110-02-L-D  [Samtec_RSM-110-02-x-D]
J10  2059-302/998-403  [WAGO_2059-302]  (value not drawn)
J11  2059-302/998-403  [WAGO_2059-302]  (value not drawn)
J12  RSM-110-02-L-D  [Samtec_RSM-110-02-x-D]
J13  HTSW-105-07-G-S  [Samtec_HTSW-105-07-G-S]  (value not drawn)
J14  2059-302/998-403  [WAGO_2059-302]  (value not drawn)
L1  74279220601  [0805_HV]  (value not drawn)
L2  74279220601  [0805_HV]  (value not drawn)
L3  74279220601  [0805_HV]  (value not drawn)
L4  74279220601  [0805_HV]  (value not drawn)
L5  74279220601  [0805_HV]  (value not drawn)
R1  ValueDisplayed: 100k  [0201]  (hidden comment: RC0201FR-07100KL)
R2  ValueDisplayed: 100k  [0201]  (hidden comment: RC0201FR-07100KL)
R3  ValueDisplayed: 100k  [0201]  (hidden comment: RC0201FR-07100KL)
R4  ValueDisplayed: 100k  [0201]  (hidden comment: RC0201FR-07100KL)
R5  ValueDisplayed: 100k  [0201]  (hidden comment: RC0201FR-07100KL)
R6  ValueDisplayed: 100k  [0201]  (hidden comment: RC0201FR-07100KL)
R7  ValueDisplayed: 0.33  [0402]  (hidden comment: ERJ-2BQFR33X)
R8  ValueDisplayed: 100k  [0201]  (hidden comment: RC0201FR-07100KL)
R9  ValueDisplayed: 100k  [0201]  (hidden comment: RC0201FR-07100KL)
R10  ValueDisplayed: 100k  [0201]  (hidden comment: RC0201FR-07100KL)
R11  ValueDisplayed: 100k  [0201]  (hidden comment: RC0201FR-07100KL)
R12  ValueDisplayed: 100k  [0201]  (hidden comment: RC0201FR-07100KL)
R13  ValueDisplayed: 0.33  [0402]  (hidden comment: ERJ-2BQFR33X)
R14  ValueDisplayed: 100k  [0201]  (hidden comment: RC0201FR-07100KL)
R15  ValueDisplayed: 100k  [0201]  (hidden comment: RC0201FR-07100KL)
R16  ValueDisplayed: 100k  [0201]  (hidden comment: RC0201FR-07100KL)
R17  ValueDisplayed: 100k  [0201]  (hidden comment: RC0201FR-07100KL)
R18  ValueDisplayed: 100k  [0201]  (hidden comment: RC0201FR-07100KL)
R19  ValueDisplayed: 0.33  [0402]  (hidden comment: ERJ-2BQFR33X)
R20  ValueDisplayed: 100k  [0201]  (hidden comment: RC0201FR-07100KL)
R21  ValueDisplayed: 100k  [0201]  (hidden comment: RC0201FR-07100KL)
R22  ValueDisplayed: 100k  [0201]  (hidden comment: RC0201FR-07100KL)
R23  ValueDisplayed: 0  [0201]  (hidden comment: CRCW02010000Z0ED)
R24  ValueDisplayed: 0  [0201]  (hidden comment: CRCW02010000Z0ED)
R25  ValueDisplayed: 100k  [0201]  (hidden comment: RC0201FR-07100KL)
R26  ValueDisplayed: 100k  [0201]  (hidden comment: RC0201FR-07100KL)
R27  ValueDisplayed: 100k  [0201]  (hidden comment: RC0201FR-07100KL)
R28  ValueDisplayed: 100k  [0201]  (hidden comment: RC0201FR-07100KL)
R29  ValueDisplayed: 100k  [0201]  (hidden comment: RC0201FR-07100KL)
R30  ValueDisplayed: 0  [0201]  (hidden comment: CRCW02010000Z0ED)
R31  ValueDisplayed: 0  [0201]  (hidden comment: CRCW02010000Z0ED)
R32  ValueDisplayed: 0  [0201]  (hidden comment: CRCW02010000Z0ED)
R33  ValueDisplayed: 0.33  [0402]  (hidden comment: ERJ-2BQFR33X)
R34  ValueDisplayed: 0  [0201]  (hidden comment: CRCW02010000Z0ED)
R35  ValueDisplayed: 0  [0201]  (hidden comment: CRCW02010000Z0ED)
R36  ValueDisplayed: 0  [0201]  (hidden comment: CRCW02010000Z0ED)
R37  ValueDisplayed: 0  [0201]  (hidden comment: CRCW02010000Z0ED)
R38  ValueDisplayed: 0  [0201]  (hidden comment: CRCW02010000Z0ED)
R39  ValueDisplayed: 0  [0201]  (hidden comment: CRCW02010000Z0ED)
R40  ValueDisplayed: 0  [0201]  (hidden comment: CRCW02010000Z0ED)
R41  ValueDisplayed: 0  [0201]  (hidden comment: CRCW02010000Z0ED)
R42  ValueDisplayed: 0  [0201]  (hidden comment: CRCW02010000Z0ED)
R43  ValueDisplayed: 0  [0201]  (hidden comment: CRCW02010000Z0ED)
R44  ValueDisplayed: 100k  [0201]  (hidden comment: RC0201FR-07100KL)
R45  ValueDisplayed: 100k  [0201]  (hidden comment: RC0201FR-07100KL)
R46  ValueDisplayed: 0  [0201]  (hidden comment: CRCW02010000Z0ED)
R47  ValueDisplayed: 0  [0201]  (hidden comment: CRCW02010000Z0ED)
R48  ValueDisplayed: 100k  [0201]  (hidden comment: RC0201FR-07100KL)
R49  ValueDisplayed: 0  [0201]  (hidden comment: CRCW02010000Z0ED)
R50  ValueDisplayed: 100k  [0201]  (hidden comment: RC0201FR-07100KL)
R51  ValueDisplayed: 100k  [0201]  (hidden comment: RC0201FR-07100KL)
R52  ValueDisplayed: 0.33  [0402]  (hidden comment: ERJ-2BQFR33X)
TP1  RCU-0C  [TE_RCU]
TP2  RCU-0C  [TE_RCU]
TP3  RCU-0C  [TE_RCU]
TP4  RCU-0C  [TE_RCU]  (value not drawn)
TP5  RCU-0C  [TE_RCU]
TP6  RCU-0C  [TE_RCU]  (value not drawn)
TP7  RCU-0C  [TE_RCU]
TP8  RCU-0C  [TE_RCU]
TP9  RCU-0C  [TE_RCU]  (value not drawn)
TP10  RCU-0C  [TE_RCU]
TP11  RCU-0C  [TE_RCU]  (value not drawn)
TP12  RCU-0C  [TE_RCU]
TP13  RCU-0C  [TE_RCU]
TP14  RCU-0C  [TE_RCU]
TP15  RCU-0C  [TE_RCU]  (value not drawn)
TP16  RCU-0C  [TE_RCU]
TP17  RCU-0C  [TE_RCU]
TP18  RCU-0C  [TE_RCU]
TP19  RCU-0C  [TE_RCU]  (value not drawn)
TP20  RCU-0C  [TE_RCU]
TP21  RCU-0C  [TE_RCU]
TP22  RCU-0C  [TE_RCU]  (value not drawn)
TP23  RCU-0C  [TE_RCU]  (value not drawn)
TP24  RCU-0C  [TE_RCU]  (value not drawn)
TP25  RCU-0C  [TE_RCU]  (value not drawn)
TP26  RCU-0C  [TE_RCU]  (value not drawn)
U1  TPS22976DPUR  [DPU0014A]
U2  TCA9535RTWR  [RTW0024B]

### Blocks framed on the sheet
EN / PG Sequencing: R1-R6 R8-R12 R14-R18 R20-R22 R25 R26 R44 R45 R50 R51 TP1-TP3 TP5 TP7 TP8 TP10 TP12-TP14 TP16-TP18 TP20 TP21
Power Gating: C4-C9 TP6 TP9 U1
Output Filters (Optional): C1-C3 C10-C18 C20-C22 J1-J8 J10 J11 J14 L1-L5 R7 R13 R19 R33 R52 TP4 TP11 TP15 TP19 TP22-TP26
I2C to EN / PG: C19 R23 R24 R27-R32 R34-R43 R46-R49 U2
Bottom Entry Connectors: J9 J12

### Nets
1V1: C21.1 J9.3 J9.4 J14.2 L5.2 R52.2 TP22.1
1V2: C17.1 J10.2 L4.2 R33.2 TP19.1
1V8: C11.1 J2.2 J9.7 J9.8 L2.2 R13.2 TP11.1
1V35: C14.1 J6.2 J9.5 J9.6 L3.2 R19.2 TP15.1
3V3: C2.1 C6.1 C19.1 J1.2 J9.9 J9.10 L1.2 R3.1 R6.1 R7.2 R12.1 R16.1 R20.1 R27.2 R28.2 R29.2 R48.1 TP4.1 U1.6(VIN2) U1.7(VIN2) U2.21(VCC)
G3V3: C7.1 J9.11 J9.12 J11.2 TP9.1 U1.8(VOUT2) U1.9(VOUT2)
G5V: C4.1 J8.2 J9.13 J9.14 TP6.1 U1.13(VOUT1) U1.14(VOUT1)
GND: C1.2 C2.2 C3.2 C4.2 C5.2 C6.2 C7.2 C8.2 C9.2 C10.2 C11.2 C12.2 C13.2 C14.2 C15.2 C16.2 C17.2 C18.2 C19.2 C20.2 C21.2 C22.2 J1.1 J2.1 J4.1 J5.1 J6.1 J7.1 J8.1 J9.1 J9.2 J10.1 J11.1 J12.1 J13.1 J14.1 R4.2 R5.2 R10.2 R11.2 R17.2 R18.2 R25.2 R26.2 R37.1 R38.1 R39.1 R50.2 R51.2 TP23.1 TP24.1 TP25.1 TP26.1 U1.11(GND) U1.15(PAD) U2.9(GND) U2.25(EP)
L1V8A: J5.2
L1V8B: J7.2
L2V8: J4.2
nLED: J3.1 J9.16
pLED: J3.2 J9.15
PLLUP: C5.1 R1.1 R2.1 R8.1 R9.1 R14.1 R15.1 R21.1 R22.1 R44.1 R45.1 U1.1(VIN1) U1.2(VIN1) U1.4(VBIAS)  [also labelled VDC]
EN_1V1: J12.3 R14.2 R17.1 R40.1 TP12.1 ; off-sheet EN_1V1
EN_1V2: R9.2 R11.1 R35.1 TP8.1 ; off-sheet EN_1V2
EN_1V8: J12.7 R2.2 R5.1 R30.1 TP2.1 ; off-sheet EN_1V8
EN_1V35: J12.5 R8.2 R10.1 R32.1 TP7.1 ; off-sheet EN_1V35
EN_3V3: R1.2 R4.1 R23.1 TP1.1 ; off-sheet EN_3V3
EN_G3V3: J12.9 R45.2 R49.1 R51.1 TP21.1 U1.5(ON2) ; off-sheet EN_G3V3
EN_G5V: J12.11 R44.2 R47.1 R50.1 TP20.1 U1.3(ON1) ; off-sheet EN_G5V
EN_L1V8A: R21.2 R25.1 R43.1 TP17.1 ; off-sheet EN_L1V8A
EN_L1V8B: R22.2 R26.1 R46.1 TP18.1 ; off-sheet EN_L1V8B
EN_L2V8: R15.2 R18.1 R42.1 TP13.1 ; off-sheet EN_L2V8
I2C_INT: J12.6 J13.3 R48.2 U2.22(~{INT}) ; off-sheet I2C_INT
LED_PWM: J12.8 J13.2 ; off-sheet LED_PWM
PG_1V1: J12.10 R20.2 R41.1 TP16.1 ; off-sheet PG_1V1
PG_1V2: R16.2 R36.1 TP14.1 ; off-sheet PG_1V2
PG_1V8: J12.14 R6.2 R31.1 TP5.1 ; off-sheet PG_1V8
PG_1V35: J12.12 R12.2 R34.1 TP10.1 ; off-sheet PG_1V35
PG_3V3: J12.16 R3.2 R24.1 TP3.1 ; off-sheet PG_3V3
SCL: J12.4 J13.5 U2.19(SCL) ; off-sheet SCL
SDA: J12.2 J13.4 U2.20(SDA) ; off-sheet SDA
V1V1: C20.1 L5.1 ; off-sheet V1V1
V1V2: C16.1 L4.1 ; off-sheet V1V2
V1V8: C10.1 L2.1 ; off-sheet V1V8
V1V35: C13.1 L3.1 ; off-sheet V1V35
V3V3: C1.1 L1.1 ; off-sheet V3V3
NetC3_1: C3.1 R7.1
NetC8_1: C8.1 U1.12(CT1)
NetC9_1: C9.1 U1.10(CT2)
NetC12_1: C12.1 R13.1
NetC15_1: C15.1 R19.1
NetC18_1: C18.1 R33.1
NetC22_1: C22.1 R52.1
NetR23_2: R23.2 U2.1(P00)
NetR24_2: R24.2 U2.2(P01)
NetR27_1: R27.1 R37.2 U2.18(A0)
NetR28_1: R28.1 R38.2 U2.23(A1)
NetR29_1: R29.1 R39.2 U2.24(A2)
NetR30_2: R30.2 U2.3(P02)
NetR31_2: R31.2 U2.4(P03)
NetR32_2: R32.2 U2.5(P04)
NetR34_2: R34.2 U2.6(P05)
NetR35_2: R35.2 U2.7(P06)
NetR36_2: R36.2 U2.8(P07)
NetR40_2: R40.2 U2.10(P10)
NetR41_2: R41.2 U2.11(P11)
NetR42_2: R42.2 U2.12(P12)
NetR43_2: R43.2 U2.13(P13)
NetR46_2: R46.2 U2.14(P14)
NetR47_2: R47.2 U2.15(P15)
NetR49_2: R49.2 U2.16(P16)

Not connected (* = marked no-connect by the designer): J9 17 18 19 20; J12 13 15 17 18 19 20; U2 17(P17)

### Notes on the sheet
- 5V / 3V3 Load Switch
- Copper pad for thermals
- I2C Expander
- (near R37) Address selection
- Optional Configurations
- RC Delay
- MCU Control

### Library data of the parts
C1 C10 C13 C16 C20 = CMP-0006203-2: CAP, CERM, 0.01 uF, 10 V, +/- 10%, X7R, 0402; Manufacturer: AVX; TaMin_C: -55°C; Polarized: N; SizeAreaWB_mm2: 3; Value1: Unknown; U/M: EA; Value: 0.01uF; TaMax_C: 125°C; SizeZ_mm: 0.6; SizeX_mm: 1; SizeY_mm: 0.5; Cap_F: 10nF; AEC Category: Q200
C2 C11 C14 C17 C21 = CMP-0007318-5: CAP, CERM, 10 uF, 10 V, +/- 20%, X5R, 0603; Manufacturer: MuRata; TaMin_C: -55°C; Polarized: N; SizeAreaWB_mm2: 4.68; Value1: Unknown; U/M: EA; Value: 10uF; TaMax_C: 85°C; SizeZ_mm: 1; SizeX_mm: 1.6; SizeY_mm: 0.8; SizeArea_mm2: 1.28; Cap_F: 10µF; AEC Category: Q200
C3 C12 C15 C18 C22 = CMP-0078699-1: CAP, CERM, 47 µF, 10 V,+/- 20%, X5R, 0805; Manufacturer: MuRata; TaMin_C: -55°C; Polarized: N; Green_Lifecycle: Active; SizeAreaWB_mm2: 6.75; Green_REACh: Passed; U/M: EA; Value: 47uF; TaMax_C: 85°C; SizeZ_mm: 1.45; SizeX_mm: 2; SizeY_mm: 1.25; Cap_Case: 0805; SizeArea_mm2: 2.5; AEC Category: Q200
C4 = CMP-0007379-4: CAP, CERM, 1 uF, 16 V, +/- 10%, X7R, 0603; Manufacturer: MuRata; TaMin_C: -55°C; ESR_ohm: 0.011; Polarized: N; SizeAreaWB_mm2: 4.68; Value1: 0.011 ohm; U/M: EA; Value: 1uF; TaMax_C: 125°C; SizeZ_mm: 1; SizeX_mm: 1.6; SizeY_mm: 0.8; SizeArea_mm2: 1.28; Cap_F: 1µF; AEC Category: Q200
C5 C6 = CMP-0064936-4: as C27 on sheet TIDA-01579 Point of Load
C7 = CMP-0007365-4: CAP, CERM, 1 uF, 10 V, +/- 10%, X7R, 0603; Manufacturer: MuRata; TaMin_C: -55°C; ESR_ohm: 0.011; Polarized: N; SizeAreaWB_mm2: 4.68; Value1: 0.011 ohm; U/M: EA; Value: 1uF; TaMax_C: 125°C; SizeZ_mm: 1; SizeX_mm: 1.6; SizeY_mm: 0.8; SizeArea_mm2: 1.28; Cap_F: 1µF; AEC Category: Q200
C8 C9 = CMP-0009636-3: CAP, CERM, 1000 pF, 25 V, +/- 10%, X5R, 0201; Manufacturer: TDK; TaMin_C: -55°C; Polarized: N; SizeAreaWB_mm2: 2.08; Value1: Unknown; U/M: EA; Value: 1000pF; TaMax_C: 85°C; SizeZ_mm: 0.33; SizeX_mm: 0.6; SizeY_mm: 0.3; Cap_Case: 0201; SizeArea_mm2: 0.18; Cap_F: 1nF; AEC Category: Q200
C19 = CMP-0064927-2: CAP, CERM, 1 uF, 10 V,+/- 20%, X5R, 0402; Manufacturer: MuRata; TaMin_C: -55°C; Polarized: N; SizeAreaWB_mm2: 3; Value1: Unknown; U/M: EA; Value: 1uF; TaMax_C: 85°C; SizeZ_mm: 0.6; SizeX_mm: 1; SizeY_mm: 0.5; Cap_F: 1µF; AEC Category: Q200
J1-J8 J10 J11 J14 = CMP-0075342-1: as J15 on sheet TIDA-01579 Point of Load
J9 J12 = CMP-0081743-1: Receptacle, 1.27mm, 10x2, Gold with Tin tail, SMT; Manufacturer: Samtec; Pitch_mm: 1.27; Gender: Female; Cert_UL: Y; Current_A: 3.1A; RowSpacing_mm: 2.54; Row_Count: 2; CompType: Socket Strip
J13 = CMP-0075485-1: Header, 100mil, 5x1, Gold, TH; Manufacturer: Samtec; Green_REACh: Passed; CT: False; Green_Lifecycle: Active; CNHeader: True
L1-L5 = CMP-0003136-1: Ferrite Bead, 600 ohm @ 100 MHz, 2.1 A, 0805; Manufacturer: Wurth Elektronik; Ztyp@1GHz_Ohm: 101.062; ZTyp@100MHz_Ohm: 600; SizeAreaWB_mm2: 6.75; DCR_ohm: 0.043; Value1: 0.043 ohm; Value: 600 ohm; Imax_A: 2.1A; SizeZ_mm: 1.45; SizeX_mm: 2; SizeY_mm: 1.25; SizeArea_mm2: 2.5
R1-R6 R8-R12 R14-R18 R20-R22 R25-R29 R44 R45 R48 R50 R51 = CMP-0027293-2: as R56 on sheet TIDA-01579 Point of Load
R7 R13 R19 R33 R52 = CMP-0026635-1: RES, 0.33, 1%, 0.125 W, 0402; Manufacturer: Panasonic; Power_W: 125mW; TempCo: 250 ppm/C; Value_Code: R330; U/M: EA; Value: 0.33; EIA_Code: E96; Res_ohm: 3.3d; SizeX_mm: 1; SizeY_mm: 0.5; SizeZ_mm: 0.6; Value2: 0.125W; AEC Category: Q200
R23 R24 R30-R32 R34-R43 R46 R47 R49 = CMP-0027008-4: RES, 0, 5%, 0.05 W, 0201; Manufacturer: Vishay-Dale; Power_W: 50mW; TempCo: ppm/C; Value_Code: 0000; Value: 0; EIA_Code: E24; SizeX_mm: 0.6; SizeY_mm: 0.3; SizeZ_mm: 0.26; Value2: 0.05W; SizeArea_mm2: 0.18; AEC Qualified: N; AEC Category: Q200
TP1-TP26 = CMP-0067620-1: as TP27 on sheet TIDA-01579 Point of Load
U1 = CMP-0073686-3: 5.5V, 6A, 14mΩ, Dual Load Switch with Adj. Rise Time & Optional QOD, DPU0014A (WSON-14); Alternate PartNumber: TPS22976DPUT; Alternate Manufacturer: Texas Instruments; Green_Lifecycle: Active; SizeAreaWB_mm2: 12.0; Green_REACh: Passed; SizeZ_mm: 0.8; SizeX_mm: 2.0; SizeY_mm: 3.0; SizeArea_mm2: 6.0; CompType: IC; AEC Category: Q200; AEC Qualified: N
U2 = CMP-0043177-2: Remote 16-Bit I2C and SMBus, Low-Power I/O Expander with Interrupt Output and Config Register, 1.65 to 5.5 V, -40 to 85 degC, 24-pin QFN (RTW), Green (RoHS & no Sb/Br); Manufacturer: Texas Instruments; SubFamily: I2C IO Expander; 5V Tolerant I/O: Yes; Max Frequency(kHz): 400; # of I/Os: 16; I2C Address: 0100 xxx

## Sheet EVM_Hardware.SchDoc
size 431 x 279 mm; Date: Not shown in title block; ApprovedBy: Not shown in title block; CheckedBy: Not shown in title block; Author: Not shown in title block; CompanyName: Not shown in title block; Engineer: Not shown in title block; Organization: Not shown in title block; Address1: Not shown in title block; Address2: Not shown in title block; Address3: Not shown in title block; Address4: Not shown in title block; DocumentNumber: 1; Revision: Use project parameter SCH_Rev; SheetNumber: 3; SheetTotal: 3; PageSetup: Record=PageOptions¦CenterHorizontal=True¦CenterVertical=True¦PrintScale=1.00¦XCorrection=1.00¦YCorrection=1.00¦PrintKind=0¦BorderSize=5000000¦LeftOffset=0¦BottomOffset=0¦Orientation=2¦PaperLength=1000¦PaperWidth=1000¦Scale=100¦PaperSource=15¦PrintQuality=600¦MediaType=1¦DitherType=10¦PaperKind=Letter¦PrintScaleMode=1
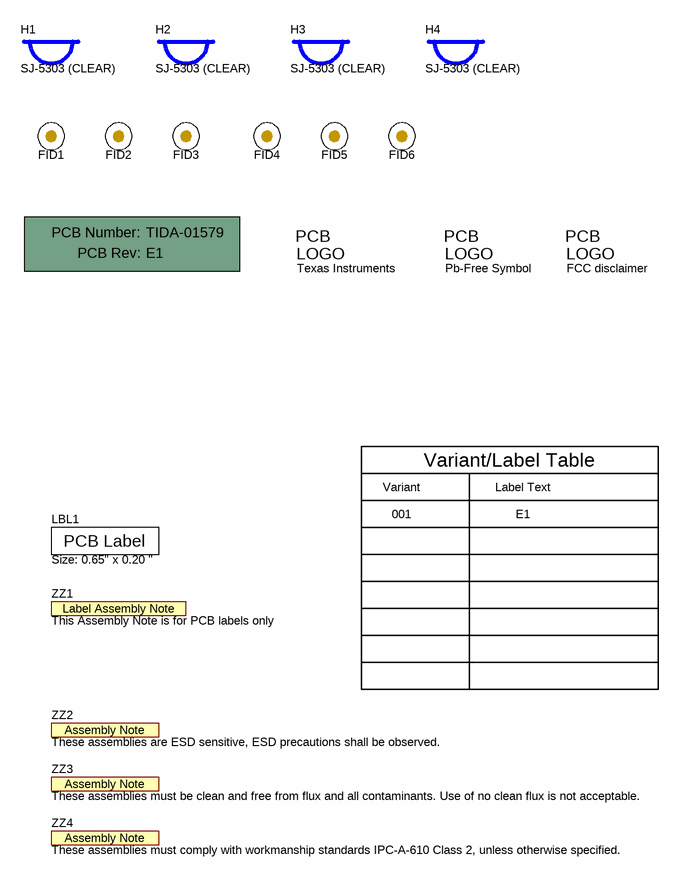
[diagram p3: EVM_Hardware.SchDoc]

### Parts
!PCB1  Printed Circuit Board  (value not drawn)  (mechanical)
FID1  Fiducial  [Fiducial10-20]  (value not drawn)
FID2  Fiducial  [Fiducial10-20]  (value not drawn)
FID3  Fiducial  [Fiducial10-20]  (value not drawn)
FID4  Fiducial  [Fiducial10-20]  (value not drawn)
FID5  Fiducial  [Fiducial10-20]  (value not drawn)
FID6  Fiducial  [Fiducial10-20]  (value not drawn)
H1  SJ-5303 (CLEAR)  [Bumpon_SJ5003Transparent]
H2  SJ-5303 (CLEAR)  [Bumpon_SJ5003Transparent]
H3  SJ-5303 (CLEAR)  [Bumpon_SJ5003Transparent]
H4  SJ-5303 (CLEAR)  [Bumpon_SJ5003Transparent]
LBL1  Size: 0.65" x 0.20 "  [Label_650x200]
Logo1  Texas Instruments  [TI_Stacked_Overlay_Small]  (no BOM)
Logo2  Pb-Free Symbol  [Pb-Free_Overlay_Small]  (no BOM)
Logo3  FCC disclaimer  [FCC_disclaimer]  (no BOM)
ZZ1  This Assembly Note is for PCB labels only  [AssemblyNoteLabel]  (no BOM)
ZZ2  These assemblies are ESD sensitive, ESD precautions shall be observed.  [AssemblyNote]  (no BOM)
ZZ3  These assemblies must be clean and free from flux and all contaminants. Use of no clean flux is not acceptable.  [AssemblyNote]  (no BOM)
ZZ4  These assemblies must comply with workmanship standards IPC-A-610 Class 2, unless otherwise specified.  [AssemblyNote]  (no BOM)

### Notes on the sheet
- Variant
- Variant/Label Table
- Label Text
- 001
- E1

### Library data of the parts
!PCB1 = PCB: Manufacturer: Any; PartNumber: TIDA-01579; SymbolCreator: a0412235
FID1-FID6 = Fiducial: Fiducial mark.  There is nothing to buy or mount.; SymbolCreator: codlsc
H1-H4 = SJ-5303 (CLEAR): Bumpon, Hemisphere, 0.44 X 0.20, Clear; Manufacturer: 3M; SymbolCreator: a0412235
LBL1 = THT-14-423-10: Thermal Transfer Printable Labels, 0.650" W x 0.200" H - 10,000 per roll; Manufacturer: Brady; SymbolCreator: a0412235; CompType: Label
Logo1 = TI_Logo: Texas Instrument Corporate Signature; SymbolCreator: codlsc
Logo2 = Pb-Free: SymbolCreator: a0412235
Logo3 = FCC_disclaimer: SymbolCreator: codlsc
ZZ1 = AssemblyNoteLabel: SymbolCreator: a0412235
ZZ2-ZZ4 = AssemblyNote: SymbolCreator: codlsc

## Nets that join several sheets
3V3: TIDA-01579 Point of Load (R59.1 R63.1 R67.1), TIDA-01579 Other (21 pins)
GND: TIDA-01579 Point of Load (39 pins), TIDA-01579 Other (57 pins)
L1V8A: TIDA-01579 Point of Load (C35.1 TP31.1 U7.1), TIDA-01579 Other (J5.2)
L1V8B: TIDA-01579 Point of Load (C40.1 TP33.1 U9.1), TIDA-01579 Other (J7.2)
L2V8: TIDA-01579 Point of Load (C31.1 TP29.1 U5.1), TIDA-01579 Other (J4.2)
nLED: TIDA-01579 Point of Load (R72.1 U11.3), TIDA-01579 Other (J3.1 J9.16)
pLED: TIDA-01579 Point of Load (C44.1 D1.1), TIDA-01579 Other (J3.2 J9.15)
PLLUP: TIDA-01579 Point of Load (7 pins), TIDA-01579 Other (14 pins)
EN_1V1: TIDA-01579 Point of Load (U10.1), TIDA-01579 Other (5 pins)
EN_1V2: TIDA-01579 Point of Load (U4.5), TIDA-01579 Other (R9.2 R11.1 R35.1 TP8.1)
EN_1V8: TIDA-01579 Point of Load (U6.5), TIDA-01579 Other (5 pins)
EN_1V35: TIDA-01579 Point of Load (U8.5), TIDA-01579 Other (5 pins)
EN_3V3: TIDA-01579 Point of Load (U3.1), TIDA-01579 Other (R1.2 R4.1 R23.1 TP1.1)
EN_L1V8A: TIDA-01579 Point of Load (U7.3), TIDA-01579 Other (R21.2 R25.1 R43.1 TP17.1)
EN_L1V8B: TIDA-01579 Point of Load (U9.3), TIDA-01579 Other (R22.2 R26.1 R46.1 TP18.1)
EN_L2V8: TIDA-01579 Point of Load (U5.3), TIDA-01579 Other (R15.2 R18.1 R42.1 TP13.1)
LED_PWM: TIDA-01579 Point of Load (U11.4), TIDA-01579 Other (J12.8 J13.2)
PG_1V1: TIDA-01579 Point of Load (U10.8), TIDA-01579 Other (J12.10 R20.2 R41.1 TP16.1)
PG_1V2: TIDA-01579 Point of Load (U4.6), TIDA-01579 Other (R16.2 R36.1 TP14.1)
PG_1V8: TIDA-01579 Point of Load (U6.6), TIDA-01579 Other (J12.14 R6.2 R31.1 TP5.1)
PG_1V35: TIDA-01579 Point of Load (U8.6), TIDA-01579 Other (J12.12 R12.2 R34.1 TP10.1)
PG_3V3: TIDA-01579 Point of Load (U3.8), TIDA-01579 Other (J12.16 R3.2 R24.1 TP3.1)
V1V1: TIDA-01579 Point of Load (5 pins), TIDA-01579 Other (C20.1 L5.1)
V1V2: TIDA-01579 Point of Load (5 pins), TIDA-01579 Other (C16.1 L4.1)
V1V8: TIDA-01579 Point of Load (5 pins), TIDA-01579 Other (C10.1 L2.1)
V1V35: TIDA-01579 Point of Load (5 pins), TIDA-01579 Other (C13.1 L3.1)
V3V3: TIDA-01579 Point of Load (5 pins), TIDA-01579 Other (C1.1 L1.1)

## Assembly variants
001: not fitted FID1 FID2 FID3
Variant of TIDA-01579 E1 Project: all parts fitted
